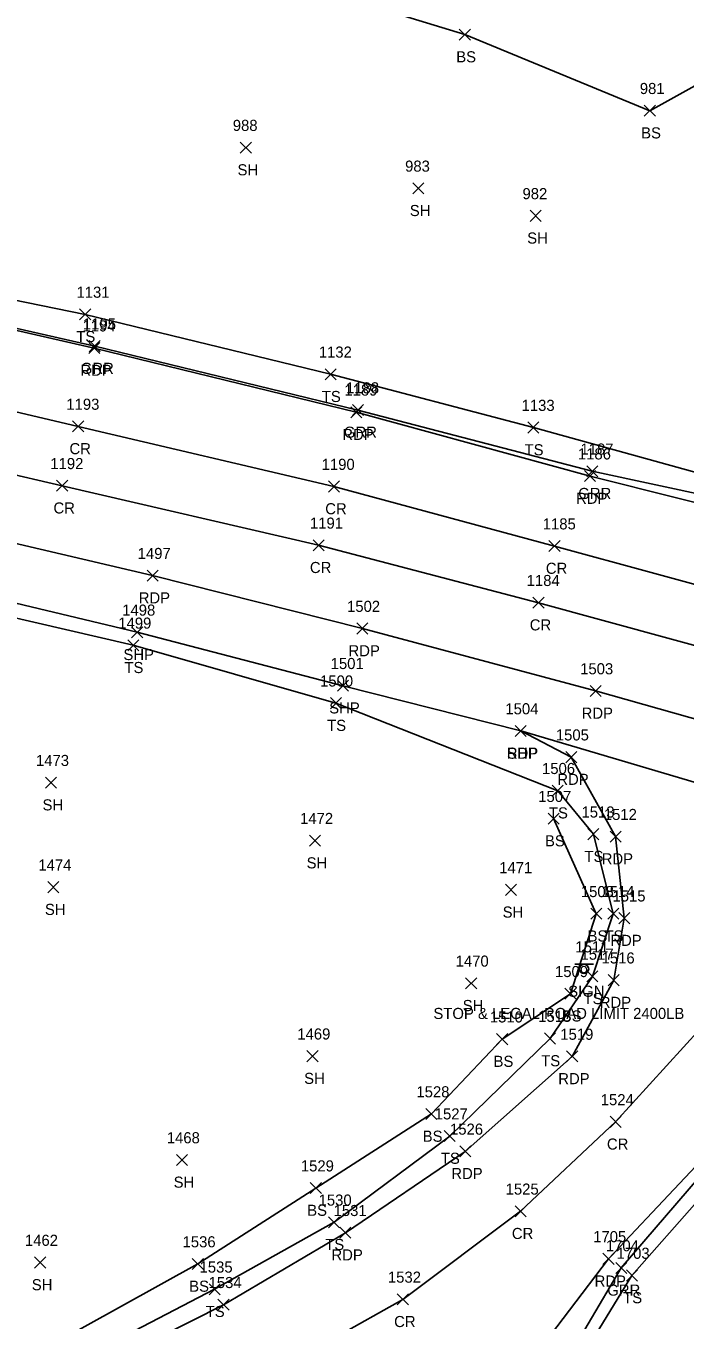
# Model space of a CAD drawing. Extents: x 1629176 to 1637209, y 606063 to 610167.
# Drawn here: x 1629782.2 to 1629900.9, y 606839.8 to 607073 of the extents above; entities that cross this region are included whole.
import ezdxf

# ---------------------------------------------------------------- set-up
doc = ezdxf.new("R2010")
doc.units = 0
for name, color, linetype in [('L_A', 7, 'Continuous'), ('L_I', 7, 'Continuous'), ('L_TIC', 7, 'Continuous'), ('LELB', 7, 'Continuous'), ('P_A', 7, 'Continuous'), ('P_I', 7, 'Continuous'), ('P_TIC', 7, 'Continuous'), ('PET', 7, 'Continuous'), ('PRC', 7, 'Continuous'), ('PSP', 7, 'Continuous'), ('R_A', 7, 'Continuous'), ('R_I', 7, 'Continuous'), ('R_TIC', 7, 'Continuous'), ('RGR', 7, 'Continuous'), ('S_A', 7, 'Continuous'), ('S_C', 7, 'Continuous'), ('S_I', 7, 'Continuous'), ('SSGN', 7, 'Continuous')]:
    doc.layers.add(name, color=color, linetype=linetype)

msp = doc.modelspace()

# ---------------------------------------------------------------- linework, layer by layer
at = {"layer": 'L_TIC'}
for points in [[(1629860.26, 607070.43), (1629862.26, 607072.43)], [(1629862.26, 607070.43), (1629860.26, 607072.43)], [(1629893.57, 607056.72), (1629895.57, 607058.72)], [(1629895.57, 607056.72), (1629893.57, 607058.72)], [(1629820.83, 607050.07), (1629822.83, 607052.07)], [(1629822.83, 607050.07), (1629820.83, 607052.07)], [(1629851.87, 607042.73), (1629853.87, 607044.73)], [(1629853.87, 607042.73), (1629851.87, 607044.73)], [(1629873, 607037.77), (1629875, 607039.77)], [(1629875, 607037.77), (1629873, 607039.77)], [(1629791.88, 607020.01), (1629793.88, 607022.01)], [(1629793.88, 607020.01), (1629791.88, 607022.01)], [(1629836.09, 607009.22), (1629838.09, 607011.22)], [(1629838.09, 607009.22), (1629836.09, 607011.22)], [(1629872.61, 606999.62), (1629874.61, 607001.62)], [(1629874.61, 606999.62), (1629872.61, 607001.62)], [(1629800.55, 606960.38), (1629802.55, 606962.38)], [(1629802.55, 606960.38), (1629800.55, 606962.38)], [(1629837.05, 606949.95), (1629839.05, 606951.95)], [(1629839.05, 606949.95), (1629837.05, 606951.95)], [(1629785.72, 606935.63), (1629787.72, 606937.63)], [(1629787.72, 606935.63), (1629785.72, 606937.63)], [(1629876.99, 606934.18), (1629878.99, 606936.18)], [(1629878.99, 606934.18), (1629876.99, 606936.18)], [(1629876.25, 606929.15), (1629878.25, 606931.15)], [(1629878.25, 606929.15), (1629876.25, 606931.15)], [(1629883.4, 606926.34), (1629885.4, 606928.34)], [(1629885.4, 606926.34), (1629883.4, 606928.34)], [(1629833.28, 606925.18), (1629835.28, 606927.18)], [(1629835.28, 606925.18), (1629833.28, 606927.18)], [(1629786.15, 606916.79), (1629788.15, 606918.79)], [(1629788.15, 606916.79), (1629786.15, 606918.79)], [(1629868.58, 606916.31), (1629870.58, 606918.31)], [(1629870.58, 606916.31), (1629868.58, 606918.31)], [(1629883.92, 606912), (1629885.92, 606914)], [(1629885.92, 606912), (1629883.92, 606914)], [(1629886.99, 606912), (1629888.99, 606914)], [(1629888.99, 606912), (1629886.99, 606914)], [(1629883.23, 606900.72), (1629885.23, 606902.72)], [(1629885.23, 606900.72), (1629883.23, 606902.72)], [(1629861.39, 606899.47), (1629863.39, 606901.47)], [(1629863.39, 606899.47), (1629861.39, 606901.47)], [(1629879.28, 606897.59), (1629881.28, 606899.59)], [(1629881.28, 606897.59), (1629879.28, 606899.59)], [(1629866.99, 606889.41), (1629868.99, 606891.41)], [(1629868.99, 606889.41), (1629866.99, 606891.41)], [(1629875.6, 606889.52), (1629877.6, 606891.52)], [(1629877.6, 606889.52), (1629875.6, 606891.52)], [(1629832.83, 606886.34), (1629834.83, 606888.34)], [(1629834.83, 606886.34), (1629832.83, 606888.34)], [(1629854.23, 606875.92), (1629856.23, 606877.92)], [(1629856.23, 606875.92), (1629854.23, 606877.92)], [(1629857.53, 606871.94), (1629859.53, 606873.94)], [(1629859.53, 606871.94), (1629857.53, 606873.94)], [(1629809.33, 606867.64), (1629811.33, 606869.64)], [(1629811.33, 606867.64), (1629809.33, 606869.64)], [(1629833.43, 606862.57), (1629835.43, 606864.57)], [(1629835.43, 606862.57), (1629833.43, 606864.57)], [(1629836.71, 606856.41), (1629838.71, 606858.41)], [(1629838.71, 606856.41), (1629836.71, 606858.41)], [(1629783.78, 606849.16), (1629785.78, 606851.16)], [(1629785.78, 606849.16), (1629783.78, 606851.16)], [(1629812.18, 606848.89), (1629814.18, 606850.89)], [(1629814.18, 606848.89), (1629812.18, 606850.89)], [(1629890.36, 606846.82), (1629892.36, 606848.82)], [(1629892.36, 606846.82), (1629890.36, 606848.82)], [(1629815.19, 606844.34), (1629817.19, 606846.34)], [(1629817.19, 606844.34), (1629815.19, 606846.34)]]:
    msp.add_lwpolyline(points, dxfattribs=at)
at = {"layer": 'LELB'}
for points in [[(1629872.74, 607605.4), (1629887.91, 607617.06), (1629901.2, 607617.32), (1629908.5, 607605.8), (1629913.9, 607581.78), (1629917.02, 607546.87), (1629916.16, 607509.81), (1629923.16, 607493.27), (1629925.16, 607453.58), (1629924.47, 607424.14), (1629903.61, 607389.66), (1629905.12, 607348.76), (1629905.7, 607299.56), (1629903.23, 607230.04), (1629906.81, 607190.46), (1629918.09, 607128.12), (1629917.39, 607086.84), (1629912.31, 607067.56), (1629894.57, 607057.72), (1629861.26, 607071.43), (1629823.99, 607082.84), (1629794.36, 607095.25), (1629802.79, 607128.03), (1629840.82, 607119.34)], [(1629543.77, 607066.01), (1629589.78, 607058.79), (1629633.94, 607051.49), (1629688.19, 607049.24), (1629712.27, 607039.3), (1629750.85, 607029.57), (1629792.88, 607021.01), (1629837.09, 607010.22), (1629873.61, 607000.62), (1629908.98, 606990.85), (1629926.95, 606990.99), (1629935.68, 606994), (1629949.32, 607001.7), (1629958.17, 607016.23), (1629963.63, 607035.3), (1629969.56, 607066.72), (1629971.34, 607098.85), (1629970.91, 607134.21), (1629967.52, 607170.11), (1629961.69, 607208.82), (1629957.6, 607251.36), (1629951.48, 607294.54)], [(1629537.12, 607012.67), (1629575, 607007.04), (1629623.31, 606998.78), (1629670.49, 606990.16), (1629714.53, 606981.27), (1629760, 606971.03), (1629801.55, 606961.38), (1629838.05, 606950.95), (1629877.99, 606935.18), (1629884.4, 606927.34), (1629887.99, 606913), (1629884.23, 606901.72), (1629876.6, 606890.52), (1629858.53, 606872.94), (1629837.71, 606857.41), (1629816.19, 606845.34), (1629787.36, 606830.32), (1629768.49, 606822.14), (1629743.52, 606814.41), (1629718.72, 606809.85), (1629691.15, 606805.56), (1629666.46, 606804.24), (1629631.78, 606804.97), (1629589.26, 606807.01)], [(1629877.25, 606930.15), (1629884.92, 606913), (1629880.28, 606898.59), (1629867.99, 606890.41), (1629855.23, 606876.92), (1629834.43, 606863.57), (1629813.18, 606849.89), (1629785.68, 606834.66), (1629767.63, 606824.5), (1629742.65, 606817.12), (1629717.54, 606811.78), (1629690.44, 606808.71), (1629665, 606806.93)], [(1630072.99, 606627.47), (1630041.99, 606654.51), (1630010.01, 606681.22), (1629981.64, 606706.28), (1629935.83, 606746.98), (1629900.42, 606776.48), (1629884.89, 606790.02), (1629879.22, 606802.61), (1629877.3, 606811.37), (1629877.5, 606819.88), (1629880.93, 606830.79), (1629891.36, 606847.82), (1629915.71, 606875.42), (1629940.9, 606902.48), (1629963.67, 606912.99), (1630002.21, 606903.33), (1630044.25, 606889.35), (1630091.41, 606872.59)]]:
    msp.add_lwpolyline(points, dxfattribs=at)
at = {"layer": 'P_TIC'}
for points in [[(1629793.53, 607013.94), (1629795.53, 607015.94)], [(1629795.53, 607013.94), (1629793.53, 607015.94)], [(1629840.7, 607002.38), (1629842.7, 607004.38)], [(1629842.7, 607002.38), (1629840.7, 607004.38)], [(1629790.63, 606999.82), (1629792.63, 607001.82)], [(1629792.63, 606999.82), (1629790.63, 607001.82)], [(1629882.8, 606990.87), (1629884.8, 606992.87)], [(1629884.8, 606990.87), (1629882.8, 606992.87)], [(1629787.74, 606989.13), (1629789.74, 606991.13)], [(1629789.74, 606989.13), (1629787.74, 606991.13)], [(1629836.69, 606988.99), (1629838.69, 606990.99)], [(1629838.69, 606988.99), (1629836.69, 606990.99)], [(1629833.93, 606978.4), (1629835.93, 606980.4)], [(1629835.93, 606978.4), (1629833.93, 606980.4)], [(1629876.41, 606978.26), (1629878.41, 606980.26)], [(1629878.41, 606978.26), (1629876.41, 606980.26)], [(1629804.04, 606972.93), (1629806.04, 606974.93)], [(1629806.04, 606972.93), (1629804.04, 606974.93)], [(1629873.52, 606968.06), (1629875.52, 606970.06)], [(1629875.52, 606968.06), (1629873.52, 606970.06)], [(1629841.82, 606963.4), (1629843.82, 606965.4)], [(1629843.82, 606963.4), (1629841.82, 606965.4)], [(1629801.25, 606962.72), (1629803.25, 606964.72)], [(1629803.25, 606962.72), (1629801.25, 606964.72)], [(1629838.3, 606953.1), (1629840.3, 606955.1)], [(1629840.3, 606953.1), (1629838.3, 606955.1)], [(1629883.8, 606952.15), (1629885.8, 606954.15)], [(1629885.8, 606952.15), (1629883.8, 606954.15)], [(1629870.33, 606944.94), (1629872.33, 606946.94)], [(1629872.33, 606944.94), (1629870.33, 606946.94)], [(1629870.33, 606944.94), (1629872.33, 606946.94)], [(1629872.33, 606944.94), (1629870.33, 606946.94)], [(1629879.42, 606940.23), (1629881.42, 606942.23)], [(1629881.42, 606940.23), (1629879.42, 606942.23)], [(1629887.42, 606925.9), (1629889.42, 606927.9)], [(1629889.42, 606925.9), (1629887.42, 606927.9)], [(1629888.97, 606911.21), (1629890.97, 606913.21)], [(1629890.97, 606911.21), (1629888.97, 606913.21)], [(1629887.08, 606900.04), (1629889.08, 606902.04)], [(1629889.08, 606900.04), (1629887.08, 606902.04)], [(1629879.59, 606886.29), (1629881.59, 606888.29)], [(1629881.59, 606886.29), (1629879.59, 606888.29)], [(1629887.42, 606874.5), (1629889.42, 606876.5)], [(1629889.42, 606874.5), (1629887.42, 606876.5)], [(1629860.33, 606869.19), (1629862.33, 606871.19)], [(1629862.33, 606869.19), (1629860.33, 606871.19)], [(1629870.3, 606858.39), (1629872.3, 606860.39)], [(1629872.3, 606858.39), (1629870.3, 606860.39)], [(1629838.75, 606854.53), (1629840.75, 606856.53)], [(1629840.75, 606854.53), (1629838.75, 606856.53)], [(1629886.14, 606849.82), (1629888.14, 606851.82)], [(1629888.14, 606849.82), (1629886.14, 606851.82)], [(1629816.8, 606841.55), (1629818.8, 606843.55)], [(1629818.8, 606841.55), (1629816.8, 606843.55)], [(1629849.1, 606842.52), (1629851.1, 606844.52)], [(1629851.1, 606842.52), (1629849.1, 606844.52)]]:
    msp.add_lwpolyline(points, dxfattribs=at)
at = {"layer": 'PET'}
for points in [[(1630115.59, 606918.47), (1630070.26, 606934.37), (1630047.19, 606942.61), (1630027.81, 606949.5), (1629999.64, 606958.79), (1629963.88, 606969.73), (1629916.37, 606983.66), (1629883.8, 606991.87), (1629841.7, 607003.38), (1629794.53, 607014.94), (1629751.13, 607024.85), (1629703.98, 607035.26), (1629666.74, 607043.02), (1629621.43, 607051.04), (1629588.28, 607056.93), (1629542.89, 607063.67), (1629493.94, 607070.34), (1629447.94, 607075.86), (1629406.53, 607080.22), (1629360.37, 607084.28), (1629316.73, 607087.48), (1629269.81, 607090.12), (1629227.29, 607092.24), (1629182.92, 607093.47)], [(1629181.97, 607055.08), (1629220.58, 607054.17), (1629264.89, 607052.3), (1629300.55, 607050.62), (1629344.63, 607047.49), (1629382.7, 607044.36), (1629427.5, 607039.91), (1629466.96, 607035.43), (1629507.21, 607030.19), (1629538.75, 607025.9), (1629578.99, 607019.69), (1629624.23, 607012.05), (1629673.21, 607003.11), (1629718.04, 606993.87), (1629764.48, 606983.46), (1629805.04, 606973.93), (1629842.82, 606964.4), (1629884.8, 606953.15), (1629930.25, 606940.34), (1629964.97, 606930.13), (1630005.89, 606916.45), (1630050.76, 606901.68), (1630096.23, 606885.67)], [(1629871.33, 606945.94), (1629880.42, 606941.23), (1629888.42, 606926.9), (1629889.97, 606912.21), (1629888.08, 606901.04), (1629880.59, 606887.29), (1629861.33, 606870.19), (1629839.75, 606855.53), (1629817.8, 606842.55), (1629788.82, 606827.89), (1629769.68, 606819.82), (1629744.49, 606811.9), (1629719.68, 606806.2), (1629691.7, 606802.76), (1629667.08, 606801.51), (1629631.79, 606801.55), (1629588.78, 606803.44)], [(1629587.14, 606776.73), (1629623.38, 606774.29), (1629651.95, 606774.51), (1629678.56, 606774.68), (1629701.14, 606776.11), (1629724.19, 606779.3), (1629746.4, 606783.99), (1629772.89, 606791.82), (1629808.22, 606801.42), (1629824.36, 606806.11), (1629835.79, 606810.93), (1629847.76, 606817.22), (1629860.47, 606825.17), (1629873.11, 606832.29), (1629887.14, 606850.82), (1629912.73, 606877.94), (1629938.57, 606904.89), (1629947.79, 606913.74), (1629954.28, 606917.5), (1629965.2, 606918.43)]]:
    msp.add_lwpolyline(points, dxfattribs=at)
at = {"layer": 'PRC'}
for points in [[(1630110.18, 606905.77), (1630065.36, 606921.68), (1630022.36, 606935.68), (1629994.71, 606945.36), (1629959.54, 606955.86), (1629913.54, 606969.37), (1629877.41, 606979.26), (1629837.69, 606989.99), (1629791.63, 607000.82), (1629746.42, 607011.44), (1629699.59, 607021.37), (1629664.04, 607028.34), (1629619.43, 607036.79), (1629585.72, 607042.18), (1629539.96, 607049.3), (1629491.45, 607056.02), (1629445.88, 607061.28), (1629404.36, 607066.23), (1629358.89, 607069.49), (1629314.63, 607073.29), (1629269.37, 607075.36), (1629226.58, 607077.32), (1629182.35, 607078.58)], [(1630105.99, 606894.95), (1630061.18, 606910.94), (1630017.61, 606925.74), (1629991.01, 606934.32), (1629955.3, 606944.84), (1629910.77, 606959.12), (1629874.52, 606969.06), (1629834.93, 606979.4), (1629788.74, 606990.13), (1629743.3, 607000.68), (1629697.98, 607010.33), (1629662.17, 607017.56), (1629618.2, 607025.81), (1629583.59, 607031.56), (1629540.4, 607037.95), (1629489.63, 607045.02), (1629444.26, 607050.14), (1629402.79, 607054.66), (1629359.1, 607058.26), (1629313.06, 607061.88), (1629268.47, 607063.97), (1629226.23, 607065.89), (1629182.22, 607066.96)], [(1629930.37, 606928.51), (1629922.33, 606915.08), (1629903.69, 606892.32), (1629888.42, 606875.5), (1629871.3, 606859.39), (1629850.1, 606843.52), (1629825.75, 606829.77), (1629796.32, 606815.42), (1629774.04, 606806.57), (1629748.19, 606798.61), (1629722.01, 606792.8), (1629693.98, 606789.27), (1629667.56, 606787.71), (1629632.27, 606787.81), (1629586.9, 606789.65)]]:
    msp.add_lwpolyline(points, dxfattribs=at)
at = {"layer": 'PSP'}
msp.add_lwpolyline([(1629181.26, 607044.82), (1629219.33, 607043.61), (1629263.7, 607041.6), (1629300.14, 607039.68), (1629342.49, 607036.76), (1629381.41, 607033.8), (1629425.61, 607029.43), (1629465.11, 607025.03), (1629505.36, 607019.79), (1629537.56, 607015.39), (1629576.08, 607009.38), (1629623.28, 607001.72), (1629671.03, 606992.73), (1629715.19, 606983.38), (1629761.23, 606973.52), (1629802.25, 606963.72), (1629839.3, 606954.1), (1629871.33, 606945.94), (1629930.37, 606928.51), (1629965.2, 606918.43), (1630003.07, 606906.25), (1630045.28, 606892.75), (1630092.08, 606875.64)], dxfattribs=at)
at = {"layer": 'R_TIC'}
for points in [[(1629793.61, 607014.29), (1629795.61, 607016.29)], [(1629795.61, 607014.29), (1629793.61, 607016.29)], [(1629841, 607002.78), (1629843, 607004.78)], [(1629843, 607002.78), (1629841, 607004.78)], [(1629883.2, 606991.74), (1629885.2, 606993.74)], [(1629885.2, 606991.74), (1629883.2, 606993.74)], [(1629888.43, 606848.18), (1629890.43, 606850.18)], [(1629890.43, 606848.18), (1629888.43, 606850.18)]]:
    msp.add_lwpolyline(points, dxfattribs=at)
at = {"layer": 'RGR'}
for points in [[(1629943.69, 607384.05), (1629950.32, 607332.08), (1629955.32, 607294.81), (1629961.02, 607247.36), (1629965.35, 607210.17), (1629970.15, 607169.34), (1629972.95, 607135.74), (1629974.05, 607104.82), (1629973.08, 607080.23), (1629970.56, 607055.99), (1629966.4, 607033.17), (1629961.24, 607015.58), (1629955.46, 607004.39), (1629949.06, 606997.06), (1629936.39, 606990.57), (1629926.1, 606987.63), (1629916.88, 606985.75), (1629884.2, 606992.74), (1629842, 607003.78), (1629794.61, 607015.29), (1629751.3, 607025.15), (1629713.98, 607033.77), (1629702.23, 607037.41), (1629690.41, 607042.59)], [(1629883.56, 606789.68), (1629877.62, 606802.29), (1629875.27, 606811.1), (1629875.33, 606819.3), (1629879.52, 606832.4), (1629889.43, 606849.18), (1629913.53, 606877.22), (1629938.73, 606904.49), (1629948.22, 606912.98), (1629955.15, 606916.34), (1629964.74, 606917.13), (1630002.73, 606905.78), (1630044.87, 606891.43), (1630091.95, 606875)]]:
    msp.add_lwpolyline(points, dxfattribs=at)
at = {"layer": 'SSGN'}
for p, q in [((1629881.09, 606903.89), (1629884.42, 606903.89)), ((1629882.73, 606903.06), (1629882.73, 606903.06))]:
    msp.add_line(p, q, dxfattribs=at)
msp.add_circle((1629882.73, 606903.06), 0.833, dxfattribs=at)

# ---------------------------------------------------------------- texts
at = {"layer": 'L_A'}
for s, p in [('BS', (1629859.71, 607066.43)), ('BS', (1629893.01, 607052.72)), ('SH', (1629820.32, 607046.07)), ('SH', (1629851.35, 607038.73)), ('SH', (1629872.49, 607033.77)), ('TS', (1629791.29, 607016.01)), ('TS', (1629835.5, 607005.22)), ('TS', (1629872.02, 606995.62)), ('TS', (1629799.96, 606956.38)), ('TS', (1629836.46, 606945.95)), ('SH', (1629785.21, 606931.63)), ('TS', (1629876.4, 606930.18)), ('BS', (1629875.69, 606925.15)), ('SH', (1629832.77, 606921.18)), ('TS', (1629882.8, 606922.34)), ('SH', (1629785.64, 606912.79)), ('SH', (1629868.07, 606912.31)), ('BS', (1629883.36, 606908)), ('TS', (1629886.4, 606908)), ('SH', (1629860.88, 606895.47)), ('TS', (1629882.64, 606896.72)), ('BS', (1629878.72, 606893.59)), ('BS', (1629866.43, 606885.41)), ('TS', (1629875.01, 606885.52)), ('SH', (1629832.32, 606882.34)), ('BS', (1629853.67, 606871.92)), ('TS', (1629856.94, 606867.94)), ('SH', (1629808.82, 606863.64)), ('BS', (1629832.87, 606858.57)), ('TS', (1629836.12, 606852.41)), ('SH', (1629783.27, 606845.16)), ('BS', (1629811.62, 606844.89)), ('TS', (1629889.77, 606842.82)), ('TS', (1629814.59, 606840.34))]:
    msp.add_text(s, height=2, dxfattribs=at).set_placement(p)
at = {"layer": 'L_I'}
for s, p in [('981', (1629892.77, 607060.72)), ('988', (1629819.47, 607054.07)), ('983', (1629850.5, 607046.73)), ('982', (1629871.64, 607041.77)), ('1131', (1629791.32, 607024.01)), ('1132', (1629834.96, 607013.22)), ('1133', (1629871.48, 607003.62)), ('1499', (1629798.85, 606964.38)), ('1500', (1629835.19, 606953.95)), ('1473', (1629784.03, 606939.63)), ('1506', (1629875.16, 606938.18)), ('1507', (1629874.48, 606933.15)), ('1513', (1629882.27, 606930.34)), ('1472', (1629831.59, 606929.18)), ('1474', (1629784.46, 606920.79)), ('1471', (1629867.45, 606920.31)), ('1508', (1629882.15, 606916)), ('1514', (1629885.86, 606916)), ('1517', (1629882.1, 606904.72)), ('1470', (1629859.61, 606903.47)), ('1509', (1629877.5, 606901.59)), ('1510', (1629865.77, 606893.41)), ('1518', (1629874.47, 606893.52)), ('1469', (1629831.09, 606890.34)), ('1528', (1629852.54, 606879.92)), ('1527', (1629855.84, 606875.94)), ('1468', (1629807.59, 606871.64)), ('1529', (1629831.73, 606866.57)), ('1530', (1629834.93, 606860.41)), ('1462', (1629782.04, 606853.16)), ('1536', (1629810.43, 606852.89)), ('1703', (1629888.59, 606850.82)), ('1535', (1629813.49, 606848.34))]:
    msp.add_text(s, height=2, dxfattribs=at).set_placement(p)
at = {"layer": 'P_A'}
for s, p in [('RDP', (1629792.02, 607009.94)), ('RDP', (1629839.19, 606998.38)), ('CR', (1629790.06, 606995.82)), ('RDP', (1629881.29, 606986.87)), ('CR', (1629787.18, 606985.13)), ('CR', (1629836.12, 606984.99)), ('CR', (1629833.36, 606974.4)), ('CR', (1629875.85, 606974.26)), ('RDP', (1629802.53, 606968.93)), ('CR', (1629872.95, 606964.06)), ('SHP', (1629799.78, 606958.72)), ('RDP', (1629840.31, 606959.4)), ('SHP', (1629836.84, 606949.1)), ('RDP', (1629882.29, 606948.15)), ('SHP', (1629868.87, 606940.94)), ('RDP', (1629868.82, 606940.94)), ('RDP', (1629877.91, 606936.23)), ('RDP', (1629885.91, 606921.9)), ('RDP', (1629887.46, 606907.21)), ('RDP', (1629885.56, 606896.04)), ('RDP', (1629878.08, 606882.29)), ('CR', (1629886.85, 606870.5)), ('RDP', (1629858.82, 606865.19)), ('CR', (1629869.73, 606854.39)), ('RDP', (1629837.24, 606850.53)), ('RDP', (1629884.63, 606845.82)), ('CR', (1629848.53, 606838.52))]:
    msp.add_text(s, height=2, dxfattribs=at).set_placement(p)
at = {"layer": 'P_I'}
for s, p in [('1194', (1629792.4, 607017.94)), ('1189', (1629839.57, 607006.38)), ('1193', (1629789.5, 607003.82)), ('1192', (1629786.62, 606993.13)), ('1186', (1629881.62, 606994.87)), ('1190', (1629835.48, 606992.99)), ('1191', (1629833.37, 606982.4)), ('1185', (1629875.29, 606982.26)), ('1497', (1629802.34, 606976.93)), ('1184', (1629872.4, 606972.06)), ('1502', (1629840.05, 606967.4)), ('1498', (1629799.56, 606966.72)), ('1501', (1629837.1, 606957.1)), ('1503', (1629882.03, 606956.15)), ('1504', (1629868.56, 606948.94)), ('1504', (1629868.56, 606948.94)), ('1505', (1629877.65, 606944.23)), ('1512', (1629886.29, 606929.9)), ('1515', (1629887.85, 606915.21)), ('1516', (1629885.89, 606904.04)), ('1519', (1629878.45, 606890.29)), ('1524', (1629885.73, 606878.5)), ('1526', (1629858.59, 606873.19)), ('1525', (1629868.61, 606862.39)), ('1531', (1629837.63, 606858.53)), ('1705', (1629884.37, 606853.82)), ('1532', (1629847.41, 606846.52)), ('1534', (1629815.11, 606845.55))]:
    msp.add_text(s, height=2, dxfattribs=at).set_placement(p)
at = {"layer": 'R_A'}
for p in [(1629792.1, 607010.29), (1629839.49, 606998.78), (1629881.69, 606987.74), (1629886.92, 606844.18)]:
    msp.add_text('GRR', height=2, dxfattribs=at).set_placement(p)
at = {"layer": 'R_I'}
for s, p in [('1195', (1629792.49, 607018.29)), ('1188', (1629839.87, 607006.78)), ('1187', (1629882.08, 606995.74)), ('1704', (1629886.66, 606852.18))]:
    msp.add_text(s, height=2, dxfattribs=at).set_placement(p)
at = {"layer": 'S_A'}
msp.add_text('SIGN', height=2, dxfattribs=at).set_placement((1629879.87, 606898.04))
at = {"layer": 'S_C'}
msp.add_text('STOP & LEGAL ROAD LIMIT 2400LB', height=2, dxfattribs=at).set_placement((1629855.6, 606894.04))
at = {"layer": 'S_I'}
msp.add_text('1511', height=2, dxfattribs=at).set_placement((1629881.16, 606906.04))

doc.saveas('drawing.dxf')
